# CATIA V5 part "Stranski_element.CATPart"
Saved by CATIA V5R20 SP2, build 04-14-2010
Part number: Stranski_element
Bounding box of the stored display mesh (mm): x -125 to 100, y -20 to 30, z 0 to 2
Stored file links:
  C:\Documents and Settings\Administrator\My Documents\Hobi_dokumenti\CAD_CNC\Clap_CATIA\Stranski_element.CATPart
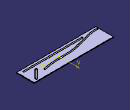
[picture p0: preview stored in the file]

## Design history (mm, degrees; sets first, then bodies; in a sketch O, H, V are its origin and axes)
Body1 (main body)
  Sketch1 on xy-plane, origin (0, 0, 0), H (1, 0, 0), V (0, 1, 0)
    line L1 (-125, 30) -> (100, 30)
    line L2 (100, 30) -> (100, -20)
    line L3 (100, -20) -> (-125, -20)
    line L4 (-125, -20) -> (-125, 30)
    distance V L4 = 125
    length L2 = 50
    distance V L2 = 100
    distance H L3 = 20
    horizontal: L1 H, L3 H
    vertical: L2 V, L4 V
  Pad1: profile Sketch1, direction (0, 0, 1), length 2
  Sketch2 on end face of Pad1, origin (0, 0, 2), H (1, 0, 0), V (0, 1, 0)
    arc A1 centre (87, 23) radius 3 from (89.1213, 20.8787) to (84.8787, 25.1213) ccw
    point P1 (87, 23)
    arc A2 centre (64.321, 0.321) radius 3 from (62.1997, 2.4423) to (66.4423, -1.8003) ccw
    point P2 (64.321, 0.321)
    line L1 (62.1997, 2.4423) -> (84.8787, 25.1213)
    line L2 (89.1213, 20.8787) -> (66.4423, -1.8003)
    line L3 (-80, -10) -> (90, -10)
    line L4 (90, -10) -> (90, -14)
    line L5 (90, -14) -> (-80, -14)
    line L6 (-80, -14) -> (-80, -10)
    reference projected line E1 (100, -20) -> (100, 30) from edge [face of Pad1 from Sketch1.L2 | end face of Pad1]
    reference projected line E2 (-125, -20) -> (100, -20) from edge [face of Pad1 from Sketch1.L3 | end face of Pad1]
    distance P1 V = 87
    distance P1 H = 23
    distance P1 P2 = 32.0729
    radius A1 = 3
    radius A2 = 3
    angle V L1 = 45
    length L5 = 170
    length L4 = 4
    distance E1 L4 = 10
    distance E2 L5 = 6
    tangency: L1 A2, L1 A1, L2 A1, L2 A2
    horizontal: L3 H, L5 H
    vertical: L4 V, L6 V
  Pocket1: profile Sketch2, direction (0, 0, -1), length 2
  Sketch3 on end face of Pad1, origin (0, 0, 2), H (1, 0, 0), V (0, 1, 0)
    spline S1 through (-123.1467, -14.1394) (-99.488, -12.7481) (-81.6529, -8.2388) (-59.434, -2.5417) (-38.5444, 2.206) (-14.0941, 4.1187) (24.6077, 5.3163) (52.8402, 9.7155)
    offsetcurve C1
    construction line L1 (-123.1467, -14.1394) -> (-122.7859, -10.1557)
    point P3 (-123.1467, -14.1394)
    construction line L2 through (-120.7631, -14.3552) direction (-0.9959, 0.0902)
    construction line L3 (52.8402, 9.7155) -> (51.9634, 13.6182)
    point P4 (52.8402, 9.7155)
    construction line L4 through (51.8512, 9.4933) direction (0.9757, 0.2192)
    line L5 (-123.1467, -14.1394) -> (-122.7859, -10.1557)
    point P5 (-123.1467, -14.1394)
    line L6 (52.8402, 9.7155) -> (51.9634, 13.6182)
    point P6 (52.8402, 9.7155)
    point P7 (-123.1467, -14.1394)
    point P8 (52.8402, 9.7155)
    coincidence: P7 P3, P8 P4, P7 P5, P8 P6
    tangency: L2 S1, L4 S1
    perpendicularity: L1 L2, L3 L4
  Pocket2: profile Sketch3, direction (0, 0, -1), length 2
  Fillet1: radius 2, on edge [face of Pocket1 from Sketch2.L5 | face of Pocket1 from Sketch2.L6]; edge [face of Pocket2 from Sketch3.S1 | face of Pocket2 from Sketch3.L5]; edge [face of Pocket1 from Sketch2.L6 | face of Pocket1 from Sketch2.L3]; edge [face of Pocket2 from Sketch3.L5 | face of Pocket2 from Sketch3.C1]; edge [face of Pocket2 from Sketch3.C1 | face of Pocket2 from Sketch3.L6]; edge [face of Pocket1 from Sketch2.L3 | face of Pocket1 from Sketch2.L4]; edge [face of Pocket2 from Sketch3.L6 | face of Pocket2 from Sketch3.S1]; edge [face of Pocket1 from Sketch2.L4 | face of Pocket1 from Sketch2.L5]
  Sketch4 on end face of Pad1, origin (0, 0, 2), H (1, 0, 0), V (0, 1, 0)
    line L1 (-125, 30) -> (100, 30)
    line L2 (100, 30) -> (100, -20)
    line L3 (100, -20) -> (-125, -20)
    line L4 (-125, -20) -> (-125, 30)
    distance V L4 = 125
    length L2 = 50
    distance V L2 = 100
    distance H L3 = 20
    horizontal: L1 H, L3 H
    vertical: L2 V, L4 V
  Pad2: profile Sketch4, direction (0, 0, 1), length 2
  Sketch5 on end face of Pad1, origin (0, 0, 2), H (1, 0, 0), V (0, 1, 0)
    line L1 (-125, 30) -> (100, 30)
    line L2 (100, 30) -> (100, -20)
    line L3 (100, -20) -> (-125, -20)
    line L4 (-125, -20) -> (-125, 30)
    distance V L4 = 125
    length L2 = 50
    distance V L2 = 100
    distance H L3 = 20
    horizontal: L1 H, L3 H
    vertical: L2 V, L4 V
  Pad3: profile Sketch5, direction (0, 0, 1), length 2
  Sketch6 on end face of Pad1, origin (0, 0, 2), H (1, 0, 0), V (0, 1, 0)
    offset curve E1 from edge [end face of Pad1 | face of Pocket2 from Sketch3.C1]
    offset line E2 (88, -12) -> (-78, -12) from edge [end face of Pad1 | face of Pocket1 from Sketch2.L3]
    offset line E3 (87, 23) -> (64.321, 0.321) from edge [end face of Pad1 | face of Pocket1 from Sketch2.L1]
Current feature: Fillet1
